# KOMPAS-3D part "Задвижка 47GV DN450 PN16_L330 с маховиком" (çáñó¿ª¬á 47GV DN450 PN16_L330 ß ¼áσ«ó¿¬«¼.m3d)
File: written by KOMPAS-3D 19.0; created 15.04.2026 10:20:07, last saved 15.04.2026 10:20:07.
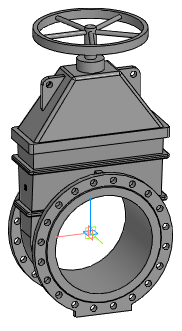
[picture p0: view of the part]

Document properties: Автор: Евгений; Полное имя файла: Z:\3.Личные\kachalov\3d для проектировщиков\2.1 Тип 47GV, 47GV.Z\Задвижка 47GV_DN40-DN600\stp_Задвижка 47GV\Задвижка 47GV DN450 PN16_L330 с маховиком.m3d

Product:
- Part/product: Задвижка 47GV DN450 PN16_L330 с маховиком

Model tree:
1. Операция без истории:1  (labels: Задвижка 47GV DN450 PN16_L330 с маховиком)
